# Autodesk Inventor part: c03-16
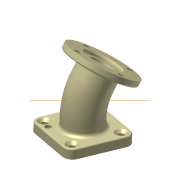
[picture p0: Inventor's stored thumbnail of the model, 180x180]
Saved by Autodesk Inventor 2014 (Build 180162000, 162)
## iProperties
Created: 2011-11
Part Number: c03-16
Material: Iron, Cast
Document SubType Name: Modeling
Designer: Thom Tremblay
Density: 7.25 g/cm^3
Mass: 1087.5 g
Surface Area: 260 cm^2
Volume: 150 cm^3
Appearance: Nylon 6
Author: Thom Tremblay
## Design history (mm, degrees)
sketch "Sketch1"
  geometry: L1 (50, -50)-(-50, -50); L2 (-50, -50)-(-50, 50); L3 (-50, 50)-(50, 50); L4 (50, 50)-(50, -50); C1 r 20 at (0, 0); C2 r 30 at (0, 0); 3 further points
  constraints: 8 end point, 2 centre point, 2 coincident, 2 midpoint, 2 parallel, 2 perpendicular, 1 horizontal, 1 horizontal alignment, 1 vertical alignment
  dimensions: "d0" = 100 distance of L2.end L3.end; "d3" = 40 diameter of C1; "d4" = 10 radial gap between concentric circles of C2 C1
extrude "Extrusion1" new body sketch "Sketch1" distance "d1" = 15; taper "d2" = 0 deg
sketch "Sketch2"
  geometry: L1 (0, 0)-(0, 30); L2 (12.794, 77.746)-(27.794, 103.727); L3 (2.558, 51.954)-(-31.505, 60); L4 (50, 0)-(-50, 0) reference; A1 r 95.493 centre (95.493, 30) between (12.794, 77.746) and (0, 30)
  constraints: 6 end point, 3 point on circle, 2 tangent, 1 centre point, 1 point on line, 1 vertical
  dimensions: "d5" = 30 distance of L1.start L1.end; "d7" = 50 dimension on A1; "d9" = 30 distance of L2.start L2.end; "d10" = 30 deg angle of L2 L1; "d87" = 35 distance of L3.start L3.end; "d88" = 60 distance from line of L4 L3.end
sketch "Sketch3"
  geometry: L1 (12.794, 77.746)-(27.794, 103.727) reference; L2 (27.794, 103.727)-(75.425, 76.227); L3 (75.425, 76.227)-(70.425, 67.567); L4 (70.425, 67.567)-(22.794, 95.067); L5 (22.794, 95.067)-(27.794, 103.727); 2 further points
  constraints: 8 end point, 2 parallel, 2 perpendicular
  dimensions: "d11" = 110 diameter of L3 L5; "d13" = 10 distance between parallel lines of L2 L4
revolve "Revolution1" sketch "Sketch3" stored, may be unused: angle "d14" = 90 deg
sweep "Sweep1" dims "d15" = 0
sweep "Sweep2" dims "d16" = 0
sketch "Sketch4"
  geometry: C1 r 55 at (0, 0) reference; C2 r 27.5 at (0, 0); 1 further point
  constraints: 1 centre point, 1 coincident
  dimensions: "d17" = 55 diameter of C2
extrude "Extrusion2" cut sketch "Sketch4" distance "d18" = 5; taper "d19" = 0 deg
fillet "Fillet1" dims "d20" = 14
fillet "Fillet2" dims "d21" = 6, "d22" = 2
chamfer "Chamfer1" distance "d23" = 2; stored, may be unused: second distance "d24" = 2, angle "d25" = 45 deg
chamfer "Chamfer2" distance "d26" = 2; stored, may be unused: second distance "d27" = 4, angle "d28" = 45 deg
hole "Hole1" diameter "d31" = 10; stored, may be unused: countersink angle "d35" = 90 deg, drill point angle "d37" = 118 deg; dims "d32" = 6, "d33" = 15, "d34" = 9, "d36" = 8, "d69" = 30, "d70" = 10
hole "Hole5" diameter "d73" = 11; stored, may be unused: countersink angle "d77" = 90 deg, drill point angle "d79" = 118 deg; dims "d71" = 10, "d72" = 10, "d74" = 6, "d75" = 20, "d76" = 2, "d78" = 8
pattern_circular "Circular Pattern1" dims angle "d39" = 360 deg
sketch "Sketch5" dims "d41" = 90
  geometry: L1 (0, 45)-(45, 0); L2 (45, 0)-(0, -45); L3 (0, -45)-(-45, 0); L4 (-45, 0)-(0, 45); C1 r 31.235 at (0, 0); 3 further points
  constraints: 8 end point, 2 coincident, 1 centre point, 1 vertical alignment, 11 other
hole "Hole6" sketch "Sketch5" at (0, 45), (45, 0), (0, -45), (-45, 0) diameter "d80" = 8.376; stored, may be unused: countersink angle "d84" = 90 deg, drill point angle "d86" = 118 deg; dims "d81" = 6, "d82" = 4, "d83" = 2, "d85" = 8
workpoint "Work Point2"
  workaxis "Work Axis2"
body "Solid1"
